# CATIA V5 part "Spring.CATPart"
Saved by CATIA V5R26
Part number: Part1
Bounding box of the stored display mesh (mm): x -50 to 50, y -44.999 to 44.983, z -4.984 to 154.984
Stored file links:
  D:\_Deepak\CATIA\New Chapter\C19 FEA\Tutorial\TUT01\Spring.CATPart
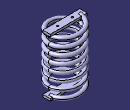
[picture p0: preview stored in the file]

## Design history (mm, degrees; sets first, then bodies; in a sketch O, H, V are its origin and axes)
Body1 (main body)
  Point1: (0, 0, 0)
  Point2: (0, 0, 150)
  Line1: type PtPt, FirstPoint Point2, SecondPoint Point1
  Point3: (40, 0, 0)
  Helix1: Direction Line1, RefPoint Point3, Pitch 20, Height 150, TaperAngle 0, Revolutions 1
  Plane1: type Normal, Curve Helix1, RefPoint vertex of Helix1, Ratio 0
  Sketch1 on Plane1, origin (0, -11.8615, 0.9439), H (1, 0, 0), V (0, 0.0793, 0.9968)
    circle A1 centre (-40, 149.5273) radius 5
    point P1 (-40, 149.5273)
    reference projected point E1 (-40, 149.5273) from vertex of Helix1
    radius A1 = 5
    coincidence: P1 E1
  Rib1: profile Sketch1, centre curve Helix1
  Sketch2 on xy-plane, origin (0, 0, 0), H (1, 0, 0), V (0, 1, 0)
    line L1 (-50, 10) -> (50, 10)
    line L2 (50, 10) -> (50, -10)
    line L3 (50, -10) -> (-50, -10)
    line L4 (-50, -10) -> (-50, 10)
    length L1 = 100
    distance L1 L3 = 20
    horizontal: L1 H, L3 H
    vertical: L2 V, L4 V
    symmetry: L3 L1 H, L2 L4 V
  Pad1: profile Sketch2, direction (0, 0, 1), length 3, mirrored extent
  Sketch3 on start face of Pad1, origin (0, 0, -3), H (1, 0, 0), V (0, -1, 0)
    circle A1 centre (-24.223, 0) radius 2.5
    point P1 (-24.223, 0)
    circle A2 centre (24.223, 0) radius 2.5
    point P2 (24.223, 0)
    radius A2 = 2.5
    coincidence: P1 H, P2 H
    symmetry: A2 A1 V
  Pocket1: profile Sketch3, direction (0, 0, 1), length 3
  Plane2: type Offset, RefPlane xy-plane, Offset 150
  Sketch4 on Plane2, origin (0, 0, 150), H (1, 0, 0), V (0, 1, 0)
    line L1 (-50, 10) -> (50, 10)
    line L2 (50, 10) -> (50, -10)
    line L3 (50, -10) -> (-50, -10)
    line L4 (-50, -10) -> (-50, 10)
    reference projected line E1 (50, -10) -> (50, 10) from edge [face of Pad1 from Sketch2.L2 | end face of Pad1]
    reference projected line E2 (-50, 10) -> (-50, -10) from edge [face of Pad1 from Sketch2.L4 | end face of Pad1]
    reference projected line E3 (-50, -10) -> (50, -10) from edge [face of Pad1 from Sketch2.L3 | end face of Pad1]
    reference projected line E4 (50, 10) -> (-50, 10) from edge [face of Pad1 from Sketch2.L1 | end face of Pad1]
    horizontal: L1 H, L3 H
    vertical: L2 V, L4 V
    coincidence: L2 E1, L4 E2, E3 L3, L1 E4
  Pad2: profile Sketch4, direction (0, 0, 1), length 3, mirrored extent
  Sketch5 on end face of Pad2, origin (0, 0, 153), H (1, 0, 0), V (0, 1, 0)
    circle A1 centre (-20.0406, 0) radius 2.5674
    point P1 (-20.0406, 0)
    circle A2 centre (20.0406, 0) radius 2.5674
    coincidence: P1 H
    symmetry: A1 A2 V
  Pocket2: profile Sketch5, direction (0, 0, -1), through (limit type 6)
